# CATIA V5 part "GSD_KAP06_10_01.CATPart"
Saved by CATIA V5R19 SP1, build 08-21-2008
Part number: GSD_LOFT_01
Definition: Beispielmodell für die Funktion Fläche mit Mehrfachschnitten / Multi-sections surface.
Description: CATIA V5 Flächenmodellierung  Copyright (c) 2009 Maik Hertha IT Consultants
Bounding box of the stored display mesh (mm): x 10 to 220.867, y -27.04 to 70.001, z -5.054 to 20.81
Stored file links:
  \GSD_BUCH_UEBUNG\GSD_KAP06_10_01.CATPart
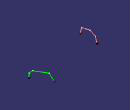
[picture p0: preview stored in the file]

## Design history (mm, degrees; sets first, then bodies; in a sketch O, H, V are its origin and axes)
AxisSystem1 "Absolute Axis System": origin (0, 0, 0), X (1, 0, 0), Y (0, 1, 0), Z (0, 0, 1)
Set1 "Loft 4"
  Plane1: type Equation, A 1, B 0, C 0, RefAxis AxisSystem1, Length 10
  Sketch1 on Plane1, origin (10, 0, 0), H (0, 1, 0), V (0, 0, 1)
    line L1 (-27.0396, -4.8684) -> (-22.2875, 14.1604)
    line L2 (-22.2875, 14.1604) -> (-7.9956, 17.2176)
    line L3 (-7.9956, 17.2176) -> (4.236, 19.8342)
    line L4 (4.236, 19.8342) -> (21.6606, 11.5532)
    line L5 (21.6606, 11.5532) -> (27.3129, -5.0544)
    curve C1
    parallelism: L3 L2
  Plane2: type Equation, A 0, B 0, C 1, RefAxis AxisSystem1, Length 10
  Sketch2 on Plane2, origin (0, 0, 10), H (1, 0, 0), V (0, 1, 0)
    spline S1 through (-9.3532, 23.8094) (121.5676, 21.2269) (200.6804, 53.0779)
    curve C1
  Plane3: type Normal, Curve Sketch2.C1, RefPoint {point type OnCurve, Support Sketch2.C1, Ratio 1}
  Sketch3 on Plane3, origin (200.6804, 53.0779, 10), H (-0.5068, 0.8621, 0), V (0, 0, 1)
    line L1 (-39.835, -9.7536) -> (-39.835, 2.9586)
    line L2 (-39.835, 2.9586) -> (-31.208, 10.8099)
    line L3 (-31.208, 10.8099) -> (7.2722, 10.8099)
    line L4 (7.2722, 10.8099) -> (19.6305, -9.7536)
    curve C1
    vertical: L1 V
    horizontal: L3 H
Body1 (main body)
